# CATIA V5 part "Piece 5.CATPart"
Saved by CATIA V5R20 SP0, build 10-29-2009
Part number: Piece 2
Bounding box of the stored display mesh (mm): x 0 to 10, y -62.096 to 270.703, z 74.591 to 310.284
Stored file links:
  C:\Users\Lambert\Desktop\IAO\Piece 5.CATPart
  C:\Users\Lambert\Desktop\IAO\Ass_Mon_IAO.CATProduct
  C:\Users\Lambert\Desktop\IAO\Piece2.1.CATPart
  C:\Users\Lambert\Desktop\IAO\Piece2.2.CATPart
  C:\Users\Lambert\Desktop\IAO\Piece2.3.CATPart
  C:\Users\Lambert\Desktop\IAO\Piece1.CATPart
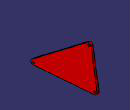
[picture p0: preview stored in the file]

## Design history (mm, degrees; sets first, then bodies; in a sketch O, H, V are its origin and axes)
Set1
  Line1 "Bielle 2.1": linked copy from another document
  Line2 "Bielle 2.2": linked copy from another document
  Line3 "Bielle 2.3": linked copy from another document
  Point1 "B": linked copy from another document
  DatumPoint1 "E": linked copy from another document
  DatumPoint2 "C": linked copy from another document
Body1 (main body)
  Sketch1 on yz-plane, origin (0, 0, 0), H (0, 1, 0), V (0, 0, 1)
    line L1 (-57.3952, 96.0542) -> (220.318, 307.71)
    line L2 (-49.198, 74.6284) -> (257.8689, 99.1172)
    line L3 (270.5212, 115.2657) -> (240.3704, 299.7293)
    point P6 (240.3704, 299.7293)
    reference projected line E1 (-50, 86.6025) -> (228.3698, 298.7587) from Line1
    reference projected line E2 (259.0188, 111.247) -> (228.3698, 298.7587) from Line2
    reference projected line E3 (259.0188, 111.247) -> (228.3698, 298.7587) from Line2
    reference projected line E4 (-50, 86.6025) -> (228.3698, 298.7587) from Line1
    reference projected line E5 (-50, 86.6025) -> (259.0188, 111.247) from Line3
    reference projected line E6 (-50, 86.6025) -> (259.0188, 111.247) from Line3
    construction line L4 (-55.6462, 157.4004) -> (-45.8256, 34.2597)
    reference projected point E7 (-50, 86.6025) from Point1
    construction line L5 (-90.129, 139.2556) -> (5.8122, 13.3714)
    reference projected point E8 (-50, 86.6025) from Point1
    construction line L6 (210.1505, 322.6642) -> (280.6275, 230.1915)
    construction line L7 (179.3394, 290.7446) -> (327.419, 314.9485)
    construction line L8 (329.5322, 122.7726) -> (189.0916, 99.8173)
    axis line L9 (247.0585, 261.2189) -> (238.2612, 371.5285)
    reference projected point E9 (228.3698, 298.7587) from DatumPoint1
    reference projected point E10 (228.3698, 298.7587) from DatumPoint1
    reference projected point E11 (259.0188, 111.247) from DatumPoint2
    reference projected point E12 (259.0188, 111.247) from DatumPoint2
    arc A1 centre (227.948, 297.6989) radius 12.5873 from (240.3704, 299.7293) to (220.318, 307.71) ccw
    point P20 (240.3704, 299.7293)
    arc A2 centre (-50.1485, 86.5457) radius 11.9552 from (-49.198, 74.6284) to (-57.3952, 96.0542) cw
    point P22 (-57.3952, 96.0542)
    arc A3 centre (256.7604, 113.0165) radius 13.9434 from (257.8689, 99.1172) to (270.5212, 115.2657) ccw
    distance L3 E3 = 12
    distance L1 E4 = 12
    distance L2 E6 = 12
    length L8 = 142.3042
    parallelism: L1 E1, L3 E2, L2 E5
    perpendicularity: L4 L2, L5 L1, L7 L3, L6 L1, L8 L3, L9 L2
    coincidence: L4 E7, L5 E8, L6 E9, L7 E10, L8 E11, L9 E12, P20 L3, A2 P22, P22 L1, P6 P20
    tangency: A1 L1, A3 L2, L3 A3, A1 L3, L2 A2, L1 A2
  Pad1: profile Sketch1, direction (1, 0, 0), length 10
  Sketch2 on end face of Pad1, origin (10, 182.5225, 189.6078), H (0, 1, 0), V (0, 0, 1)
    point P1 (-232.5225, -103.0053)
    reference projected point E1 (-232.5225, -103.0053) from Point1
    coincidence: P1 E1
  Hole1: placed by Sketch2, at (10, -50, 86.6025) direction (-1, 0, 0), diameter 10, through (limit type 6)
  Sketch3 on end face of Pad1, origin (10, 187.648, 222.1621), H (0, 1, 0), V (0, 0, 1)
    point P1 (40.7217, 76.5967)
    reference projected point E1 (40.7217, 76.5967) from DatumPoint1
    coincidence: P1 E1
  Hole2: placed by Sketch3, at (10, 228.3698, 298.7587) direction (-1, 0, 0), diameter 10, through (limit type 6)
  Sketch4 on end face of Pad1, origin (10, 147.1388, 155.9925), H (0, 1, 0), V (0, 0, 1)
    point P1 (111.88, -44.7454)
    reference projected point E1 (111.88, -44.7454) from DatumPoint2
    coincidence: E1 P1
  Hole3: placed by Sketch4, at (10, 259.0188, 111.247) direction (-1, 0, 0), diameter 10, through (limit type 6)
